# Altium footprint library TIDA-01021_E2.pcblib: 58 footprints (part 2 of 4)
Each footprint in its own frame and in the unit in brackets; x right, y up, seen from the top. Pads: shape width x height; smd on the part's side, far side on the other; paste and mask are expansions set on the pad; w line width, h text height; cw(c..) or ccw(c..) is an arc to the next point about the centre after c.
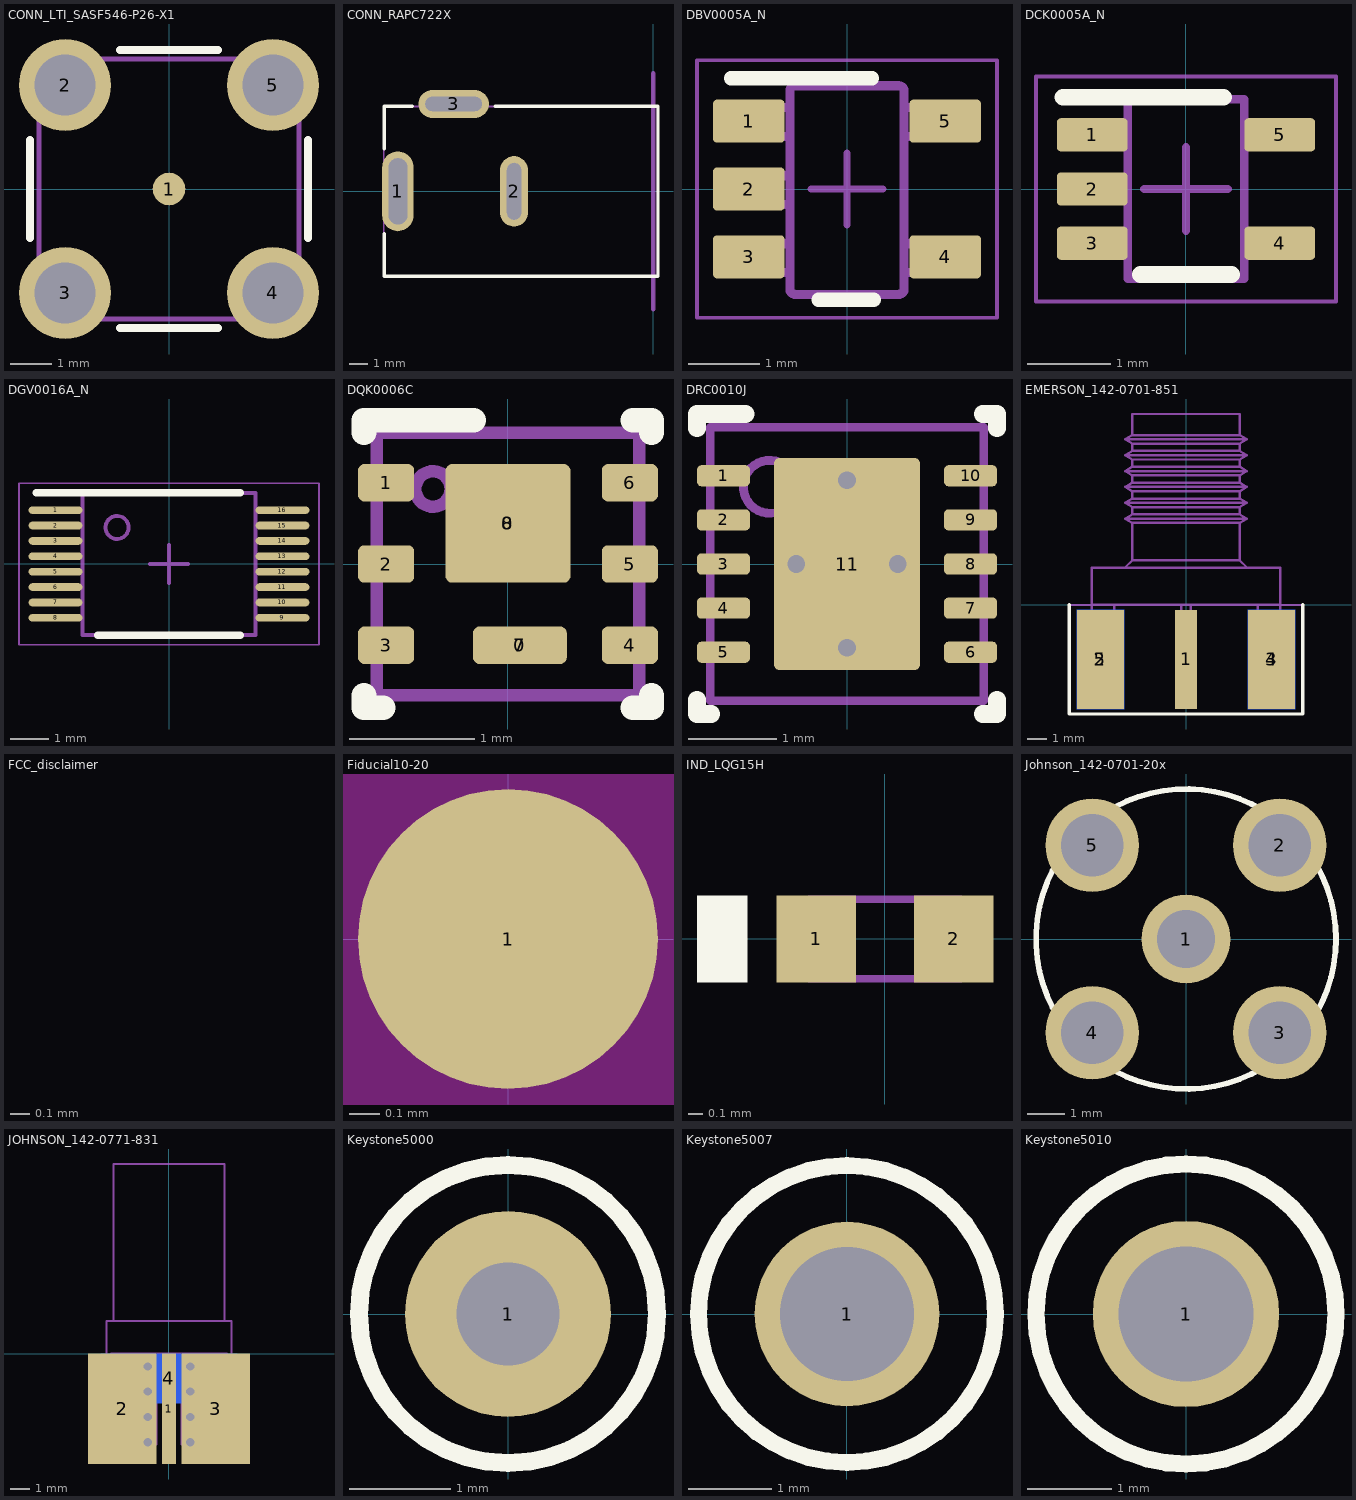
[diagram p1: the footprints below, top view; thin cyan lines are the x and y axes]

## CONN_LTI_SASF546-P26-X1 [mm]
height 12.52
pads (5):
  round 0.8 smd: 1(0,0)
  round 2.25 hole 1.5 mask+0.051: 2(-2.54,2.54) 3(-2.54,-2.54) 4(2.54,-2.54) 5(2.54,2.54)
Top Overlay:
  lines w0.2: -3.4,-1.2 -3.4,1.2 ; -1.2,-3.4 1.2,-3.4 ; -1.2,3.4 1.2,3.4 ; 3.4,-1.2 3.4,1.2
Mechanical 5:
  lines w0.127: -3.175,-3.175 3.175,-3.175 3.175,3.175 -3.175,3.175 -3.175,-3.175
  text ".Designator" at -0.508,-0.254 h0.64
Mechanical 13:
  circle w0.01: c0,0 r0.36
3D body: height 12.52, standoff 8, extent -1.865,-1.876 1.88,1.876
3D body: height 0, standoff -3.9, extent -3.05,-3.05 -2.025,-2.03
3D body: height 0, standoff -3.9, extent 2.025,-3.05 3.05,-2.03
3D body: height 0, standoff -3.9, extent 2.025,2.03 3.05,3.05
3D body: height 0.51, standoff 0, extent -3.175,1.655 -1.655,3.175
3D body: height 0.51, standoff 0, extent 1.655,1.655 3.175,3.175
3D body: height 0.51, standoff 0, extent 1.655,-3.175 3.175,-1.655
3D body: height 0, standoff -3.9, extent -3.05,2.03 -2.025,3.05
3D body: height 12.53, standoff 0.51, extent -1.587,-1.597 1.6,1.597
3D body: height 12.01, standoff 1, extent -1.613,-1.622 1.626,1.623
3D body: height 2.08, standoff 0.51, extent -3.175,-3.175 3.175,3.175
3D body: height 0.51, standoff 0, extent -0.357,-0.359 0.36,0.359
3D body: height 0.51, standoff 0, extent -3.175,-3.175 -1.655,-1.655

## CONN_RAPC722X [mm] "Conn_DC Jack"
height 11.176
pads (3):
  oval 1.7x4.3 hole 1.01 slot 3.56 at 90 deg: 1(-13.741,0)
  oval 1.5x3.8 hole 0.76 slot 3.05 at 90 deg: 2(-7.493,0)
  oval 3.8x1.5 hole 0.76 slot 3.05 at 0 deg: 3(-10.744,4.7)
Top Overlay:
  lines w0.178: -14.478,-2.286 -14.478,-4.572 0.254,-4.572 0.254,4.572 -8.509,4.572 ; -14.478,2.286 -14.478,4.572 -12.954,4.572
Mechanical 1:
  lines w0.254: 0,-6.35 0,6.35
  text "BOARD EDGE" at 1.651,-4.445 h0.89
Mechanical 5:
  lines w0.102: -14.505,-4.572 -14.505,4.572 0.227,4.572 0.227,-4.572 -14.505,-4.572
  lines w0.127: -14.443,-1.5 -13.943,-1.5 ; -14.443,1.5 -13.943,1.5 ; -13.543,-1.5 -13.943,-1.5 ; -13.543,1.5 -13.943,1.5 ; -11.993,4.5 -11.993,4.9 -9.493,4.9 -9.493,4.5 ; -13.943,-1.5 -13.943,1.5
  text ".Designator" at -12.446,-0.508 h0.64
3D body: height 5.08, standoff -2.54, extent -7.62,-1.397 -7.366,1.397
3D body: height 5.08, standoff -2.54, extent -12.14,4.573 -9.346,4.827
3D body: height 5.08, standoff -2.54, extent -14.06,-1.651 -13.425,1.651
3D body: height 11.18, standoff 0, extent -14.504,-4.571 0.226,4.571

## DBV0005A_N [mm] "SOT23, 5-Leads, Body 2.9x1.6mm, Pitch 0.95mm, Lead Span 2.8mm, IPC Medium Density"
height 1.45
pads (5):
  rrect17% 1x0.6 smd: 1(-1.375,0.95) 2(-1.375,0) 3(-1.375,-0.95) 4(1.375,-0.95) 5(1.375,0.95)
Top Overlay:
  lines w0.2: -1.625,1.55 0.35,1.55 ; -0.4,-1.55 0.375,-1.55
Mechanical 5:
  lines w0.127: -0.801,1.371 cw(c-0.725,1.37) -0.725,1.446 ; -0.801,1.37 -0.801,1.371 ; -0.801,1.37 -0.801,-1.399 -0.801,-1.4 ccw(c-0.725,-1.399) -0.725,-1.475 ; -0.725,-1.475 0.723,-1.475 0.724,-1.475 ccw(c0.723,-1.399) 0.799,-1.4 0.799,-1.399 0.799,1.37 ; -0.725,-1.475 -0.725,-1.475 ; -0.725,1.446 -0.725,1.446 ; -0.725,1.446 0.723,1.446 0.724,1.446 cw(c0.723,1.37) 0.799,1.371 ; 0.799,1.37 0.799,1.371 ; -1.423,-1.167 -1.423,-0.767 -1.199,-0.767 -1.105,-0.767 -1.088,-0.767 -0.835,-0.767 -0.801,-0.767 -0.801,-1.167 -0.835,-1.167 -1.088,-1.167 -1.105,-1.167 -1.199,-1.167 -1.423,-1.167 ; -1.423,-0.215 -1.423,0.186 -1.199,0.186 -1.105,0.186 -1.088,0.186 -0.835,0.186 -0.801,0.186 -0.801,-0.215 -0.835,-0.215 -1.088,-0.215 -1.105,-0.215 -1.199,-0.215 -1.423,-0.215 ; -1.423,0.738 -1.423,1.138 -1.199,1.138 -1.105,1.138 -1.088,1.138 -0.835,1.138 -0.801,1.138 -0.801,0.738 -0.835,0.738 -1.088,0.738 -1.105,0.738 -1.199,0.738 -1.423,0.738 ; 0.799,-1.167 0.834,-1.167 1.087,-1.167 1.103,-1.167 1.198,-1.167 1.422,-1.167 1.422,-0.767 1.198,-0.767 1.103,-0.767 1.087,-0.767 0.834,-0.767 0.799,-0.767 0.799,-1.167 ; 0.799,0.738 0.834,0.738 1.087,0.738 1.103,0.738 1.198,0.738 1.422,0.738 1.422,1.138 1.198,1.138 1.103,1.138 1.087,1.138 0.834,1.138 0.799,1.138 0.799,0.738
  text ".Designator" at 0.396,-0.768 h0.64
Mechanical 15:
  lines w0.05: -2.1,-1.8 -2.1,1.8 2.1,1.8 2.1,-1.8 -2.1,-1.8
  lines w0.1: -0.5,0 0.5,0 ; 0,-0.5 0,0.5
3D body "DBV0005A.stp": height 1.09, standoff 0, extent -1.422,-1.461 1.423,1.46

## DCK0005A_N [mm] "SOT353, 5-Leads, Body 2x1.3mm, Pitch 0.65mm, Lead Span 2.1mm, IPC Medium Density"
height 1.1
pads (5):
  rrect25% 0.85x0.4 smd: 1(-1.125,0.65) 2(-1.125,0) 3(-1.125,-0.65) 4(1.125,-0.65) 5(1.125,0.65)
Top Overlay:
  lines w0.2: -1.475,1.1 0.45,1.1 ; -0.55,-1.025 0.55,-1.025
Mechanical 5:
  lines w0.1: -0.7,-1.075 0.7,-1.075 0.7,1.075 -0.7,1.075 -0.7,-1.075
  lines w0.127: -0.865,0.762 -0.853,0.762 ; -0.711,-0.763 -0.853,-0.763 -0.865,-0.763 -0.959,-0.763 -1.143,-0.763 -1.143,-0.538 -0.959,-0.538 -0.865,-0.538 -0.853,-0.538 -0.711,-0.538 ; -0.711,-0.113 -0.853,-0.113 -0.865,-0.113 -0.959,-0.113 -1.143,-0.113 -1.143,0.112 -0.959,0.112 -0.865,0.112 -0.853,0.112 -0.711,0.112 ; -0.711,0.537 -0.853,0.537 -0.865,0.537 -0.959,0.537 -1.143,0.537 -1.143,0.762 -0.959,0.762 -0.711,0.762 ; 0.711,-0.763 0.847,-0.763 0.859,-0.763 0.953,-0.763 1.137,-0.763 1.137,-0.538 0.953,-0.538 0.859,-0.538 0.847,-0.538 0.711,-0.538 ; 0.711,0.537 0.847,0.537 0.859,0.537 0.953,0.537 1.137,0.537 1.137,0.762 0.953,0.762 0.859,0.762 0.847,0.762 0.711,0.762
  text ".Designator" at -0.254,0.824 h0.64
Mechanical 15:
  lines w0.05: -1.8,-1.35 1.8,-1.35 1.8,1.35 -1.8,1.35 -1.8,-1.35
  lines w0.1: -0.5,0 0.5,0 ; 0,-0.5 0,0.5
3D body "DCK0005A.stp": height 0.95, standoff 0, extent -1.14,-1 1.14,1

## DGV0016A_N [mm] "TSSOP, 16-Leads, Body 3.6x4.4mm, Pitch 0.4mm, IPC Medium Density"
height 1.2
pads (16):
  oval 1.4x0.2 smd: 1(-2.95,1.4) 2(-2.95,1) 3(-2.95,0.6) 4(-2.95,0.2) 5(-2.95,-0.2) 6(-2.95,-0.6) 7(-2.95,-1) 8(-2.95,-1.4) 9(2.95,-1.4) 10(2.95,-1) 11(2.95,-0.6) 12(2.95,-0.2) 13(2.95,0.2) 14(2.95,0.6) 15(2.95,1) 16(2.95,1.4)
Top Overlay:
  lines w0.2: -3.45,1.85 1.85,1.85 ; -1.85,-1.85 1.85,-1.85
Mechanical 5:
  circle w0.1: c-1.35,0.95 r0.3
  lines w0.1: -2.25,-1.85 2.25,-1.85 2.25,1.85 -2.25,1.85 -2.25,-1.85
  text ".Designator" at 0.781,-0.032 h0.64
Mechanical 15:
  lines w0.05: -3.9,-2.1 3.9,-2.1 3.9,2.1 -3.9,2.1 -3.9,-2.1
  lines w0.1: -0.5,0 0.5,0 ; 0,-0.5 0,0.5
3D body "DGV0016A.stp": height 1.2, standoff 0, extent -3.209,-1.8 3.209,1.8

## DQK0006C [mm] "WSON"
height 0.8
pads (10):
  rrect50% 0.9x0.86 on Top Paste: 0(0,0.325)
  rrect50% 0.7x0.29 on Top Paste: 0(0.095,-0.65)
  rrect33% 0.45x0.3 smd: 1(-0.975,0.65) 2(-0.975,0) 3(-0.975,-0.65) 4(0.975,-0.65) 5(0.975,0) 6(0.975,0.65)
  rrect33% 0.75x0.3 smd paste-0.15: 7(0.095,-0.65)
  rrect11% 1x0.95 smd paste-0.5: 8(0,0.325)
Top Overlay:
  lines w0.2: -1.15,-1.05 -1.15,-1.15 -1,-1.15 ; -1.15,1.05 -1.15,1.15 -0.275,1.15 ; 1,-1.15 1.15,-1.15 1.15,-1.05 ; 1,1.15 1.15,1.15 1.15,1.05
Mechanical 5:
  circle w0.1: c-0.6,0.6 r0.141
  lines w0.1: -1.05,-1.05 -1.05,1.05 1.05,1.05 1.05,-1.05 -1.05,-1.05
  text ".Designator" at -0.9,-0.4 h0.64
3D body "DQK0006C.stp": height 0.82, standoff 0, extent -1,-1 1,1

## DRC0010J [mm] "SON, 10-Leads, Body 3x3mm, Pitch 0.5mm, Thermal Pad 2.4x1.65mm, TI Recommended"
height 1
pads (11):
  rrect42% 0.6x0.24 smd: 1(-1.4,1) 2(-1.4,0.5) 3(-1.4,0) 4(-1.4,-0.5) 5(-1.4,-1) 6(1.4,-1) 7(1.4,-0.5) 8(1.4,0) 9(1.4,0.5) 10(1.4,1)
  rrect6% 1.65x2.4 smd paste-0.825: 11(0,0)
via 0,-0.95 diameter 0.5 hole 0.2
via 0,0.95 diameter 0.5 hole 0.2
via 0.575,0 diameter 0.5 hole 0.2
via -0.575,0 diameter 0.5 hole 0.2
Top Overlay:
  lines w0.2: -1.7,-1.54 -1.7,-1.7 -1.54,-1.7 ; -1.7,1.54 -1.7,1.7 -1.15,1.7 ; 1.54,-1.7 1.7,-1.7 1.7,-1.54 ; 1.54,1.7 1.7,1.7 1.7,1.54
Top Paste:
  rectangle: -0.75,-1.16 0.75,-0.1
  rectangle: -0.75,0.1 0.75,1.16
Mechanical 5:
  circle w0.1: c-0.875,0.875 r0.3
  lines w0.1: -1.55,-1.55 -1.55,1.55 1.55,1.55 1.55,-1.55 -1.55,-1.55
  text ".Designator" at 0.496,0.077 h0.64
3D body "DRC0010J.stp": height 0.77, standoff 0, extent -1.5,-1.5 1.5,1.5

## EMERSON_142-0701-851 [mil] "Johnson Components"
height 154
pads (5):
  rect 45x200 smd: 1(0,-110)
  rect 95x200 smd: 2(-172.5,-110) 3(172.5,-110)
  rect 95x200 smd far side: 4(172.5,-110) 5(-172.5,-110)
Top Overlay:
  lines w7: -235,0 -235,-220 -5,-220 235,-220 235,0
Mechanical 1:
  lines w3.94: -235,0 235,0
Mechanical 5:
  lines w5: -145,0 -145,-197 -190,-197 -190,0 ; -123.5,75 -108,90 ; -10,0 -10,-90 10,-90 10,0 ; 123.5,75 108,90 ; 145,0 145,-197 190,-197 190,0 ; -190,0 -190,75 190,75 190,0 ; -190,0 190,0 ; -123,173.9 0,173.9 123,173.9 ; -123,173.9 -108,182.56 ; -123,173.9 -108,165.24 ; -123,205.9 0,205.9 123,205.9 ; -123,205.9 -108,197.24 ; -123,205.9 -108,214.56 ; -123,237.9 0,237.9 123,237.9 ; -123,237.9 -108,246.56 ; -123,237.9 -108,229.24 ; -123,269.9 0,269.9 123,269.9 ; -123,269.9 -108,261.24 ; -123,269.9 -108,278.56 ; -123,301.9 0,301.9 123,301.9 ; -123,301.9 -108,310.56 ; -123,301.9 -108,293.24 ; -123,333.9 0,333.9 123,333.9 ; -123,333.9 -108,342.56 ; -123,333.9 -108,325.24 ; -108,90 108,90 ; -108,90 -108,165.24 ; -108,165.24 108,165.24 ; -108,182.56 108,182.56 ; -108,182.56 -108,197.24 ; -108,197.24 108,197.24 ; -108,214.56 108,214.56 ; -108,214.56 -108,229.24 ; -108,229.24 108,229.24 ; -108,246.56 108,246.56 ; -108,246.56 -108,261.24 ; -108,261.24 108,261.24 ; -108,278.56 108,278.56 ; -108,278.56 -108,293.24 ; -108,293.24 108,293.24 ; -108,310.56 108,310.56 ; -108,310.56 -108,325.24 ; -108,325.24 108,325.24 ; -108,342.56 108,342.56 ; -108,342.56 -108,385 108,385 108,342.56 ; 108,90 108,165.24 ; 108,165.24 123,173.9 ; 108,182.56 108,197.24 ; 108,182.56 123,173.9 ; 108,197.24 123,205.9 ; 108,214.56 108,229.24 ; 108,214.56 123,205.9 ; 108,229.24 123,237.9 ; 108,246.56 123,237.9 ; 108,246.56 108,261.24 ; 108,261.24 123,269.9 ; 108,278.56 123,269.9 ; 108,278.56 108,293.24 ; 108,293.24 123,301.9 ; 108,310.56 108,325.24 ; 108,310.56 123,301.9 ; 108,325.24 123,333.9 ; 108,342.56 123,333.9
  text ".Designator" at -207.2,-186.7 h25
3D body "Johnson_142-0701-851.stp": height 154.6, standoff -162.4, extent -190,-195 190,387

## FCC_disclaimer [mm]
height 9.53
Top Overlay:
  text "For evaluation only; not FCC approved for resale." at 22.86,16.866 h1.52

## Fiducial10-20 [mm]
height 9.53
pads (1):
  round 1 smd mask+0.5: 1(0,0)
Top Layer keep-out:
  circle w1.178: c0,0 r0.5

## IND_LQG15H [mm] "MuRata"
height 0.55
pads (2):
  rect 0.55x0.6 smd: 1(-0.475,0) 2(0.475,0)
Top Overlay:
  rectangle: -1.3,-0.3 -0.95,0.3
Mechanical 5:
  rectangle: -0.7,-0.274 -0.525,0.276
  lines w0.05: -0.525,-0.275 0.525,-0.275 0.525,0.275 -0.525,0.275 -0.525,-0.275
  text ".Designator" at -0.93,0.257 h0.64
3D body: height 0.55, standoff 0, extent -0.524,-0.274 -0.276,0.274
3D body: height 0.54, standoff 0, extent -0.274,-0.274 0.274,0.274
3D body: height 0.55, standoff 0, extent 0.276,-0.274 0.524,0.274
3D body: height 0.55, standoff 0.54, extent -0.274,-0.274 -0.001,0.274

## Johnson_142-0701-20x [mil] "Johnson Components recommended land pattern"
height 375
pads (5):
  round 95 hole 62: 1(0,0)
  round 100 hole 67: 2(100,100) 3(100,-100) 4(-100,-100) 5(-100,100)
Top Overlay:
  circle w6: c0,0 r160
Mechanical 5:
  circle w5: c0,0 r160
  text ".Designator" at -60,-30 h25
3D body "Emerson_142-0701-201.stp": height 375, standoff -155, extent -155.99,-155.8 156.01,155.8

## JOHNSON_142-0771-831 [mil] "JACK, SMA, 50 Ohm, Gold, Edge Mount"
height 123.5
pads (12):
  rect 28.5x218 smd: 1(0,-109)
  rect 135.75x218 smd: 2(-92.12,-109) 3(92.13,-109)
  rect 270x97.5 smd far side: 4(0,-48.75)
  round 16 hole 16: ""(-42,-175) ""(-42,-125) ""(-42,-75) ""(-42,-25) ""(42,-175) ""(42,-125) ""(42,-75) ""(42,-25)
Mechanical 5:
  circle w3.94: c0,-155 r10
  lines w3.94: -110,65 -110,375 110,375 110,65 ; -79.36,0 -79.36,-179 ; -25,-65 25,-65 ; -25,-60 25,-60 ; -25,0 -25,-179 -79.36,-179 ; -7.5,0 -7.5,-22.5 ccw(c0,-22.5) 7.5,-22.5 7.5,0 ; 25,0 25,-179 79.36,-179 ; 79.36,0 79.36,-179 ; -114.35,-179 -79.36,-179 ; -114.35,-179 -114.35,0 114.34,0 114.34,-179 ; -114.35,-179 -123.5,-179 -123.5,65 123.5,65 123.5,-179 114.34,-179 ; 79.36,-179 114.34,-179
  text ".Designator" at -175,-210 h25
3D body "142-0771-831.stp": height 130.9, standoff -116, extent -123.5,-179 123.47,375

## Keystone5000 [mil] "For Keystone 500x miniature loop terminals"
height 181.1
pads (1):
  round 80 hole 40: 1(0,0)
Top Overlay:
  circle w7: c0,0 r58
Mechanical 5:
  circle w5: c0,0 r58.31
  text ".Designator" at -10.97,42.09 h25
3D body "Keystone_5000.stp": height 181.97, standoff -118.11, extent -49,-49 49.04,49.24

## Keystone5007 [mil] "Keystone Compact loops"
height 220
pads (1):
  round 87 hole 63: 1(0,0)
Top Overlay:
  circle w7.99: c0,0 r70
Mechanical 5:
  circle w5: c0,0 r70.71
  text ".Designator" at 56.2,110.18 h25
3D body "Keystone_5007.stp": height 225.2, standoff -129.92, extent -63,-63 62.49,62.74

## Keystone5010 [mil] "Keystone Multipurpose loops"
height 320
pads (1):
  round 87 hole 63: 1(0,0)
Top Overlay:
  circle w7.99: c0,0 r70
Mechanical 5:
  circle w5: c0,0 r69.46
  text ".Designator" at 31.22,11.51 h25
3D body "Keystone_5010.stp": height 318.9, standoff -125.98, extent -63,-63 62.74,62.49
